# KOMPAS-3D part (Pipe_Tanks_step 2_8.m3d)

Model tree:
1. X Axis
2. Y Axis
3. Z Axis  (labels: Pipe Dn 50)
     Òîëùèíà ñòåíêè 1 = 1

Referenced files in C:\Documents and Settings\kashirsky\Мои документы\Camtasia Studio\Pipelines3D\Tanks\: Tanks_step 2.a3d
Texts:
  Pipe Dn 50
  Steel ASTM A295
  Three Point Plane
  Plane at Angle
  Line and Point Plane
  Axis through Two Vertices
  Axis of Feature
  Axis of Conical Surface
  Axis through Edge
  Trim by Surface
  Trim by Sketch
  Feature with No History
  Intersection Axis of Two Planes
  Two Line Plane
  Line and Face Plane
  Bend by line
  Hole in sheet body
  Cut in sheet body
  Point in CM
  Linear Dimension from Line to Point
  Surface Finish Symbol
  Geometric Tolerance Symbol
  Leader #1
  Leader #2
  Leader #3
  Shape Deviations and Datum
  Node point number
  Mark of coordination axis
  Node point designation
  Mark/Reference designation with leader
  Mark/reference designation on line
  Mark/Reference designation without leader
  Plane of section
